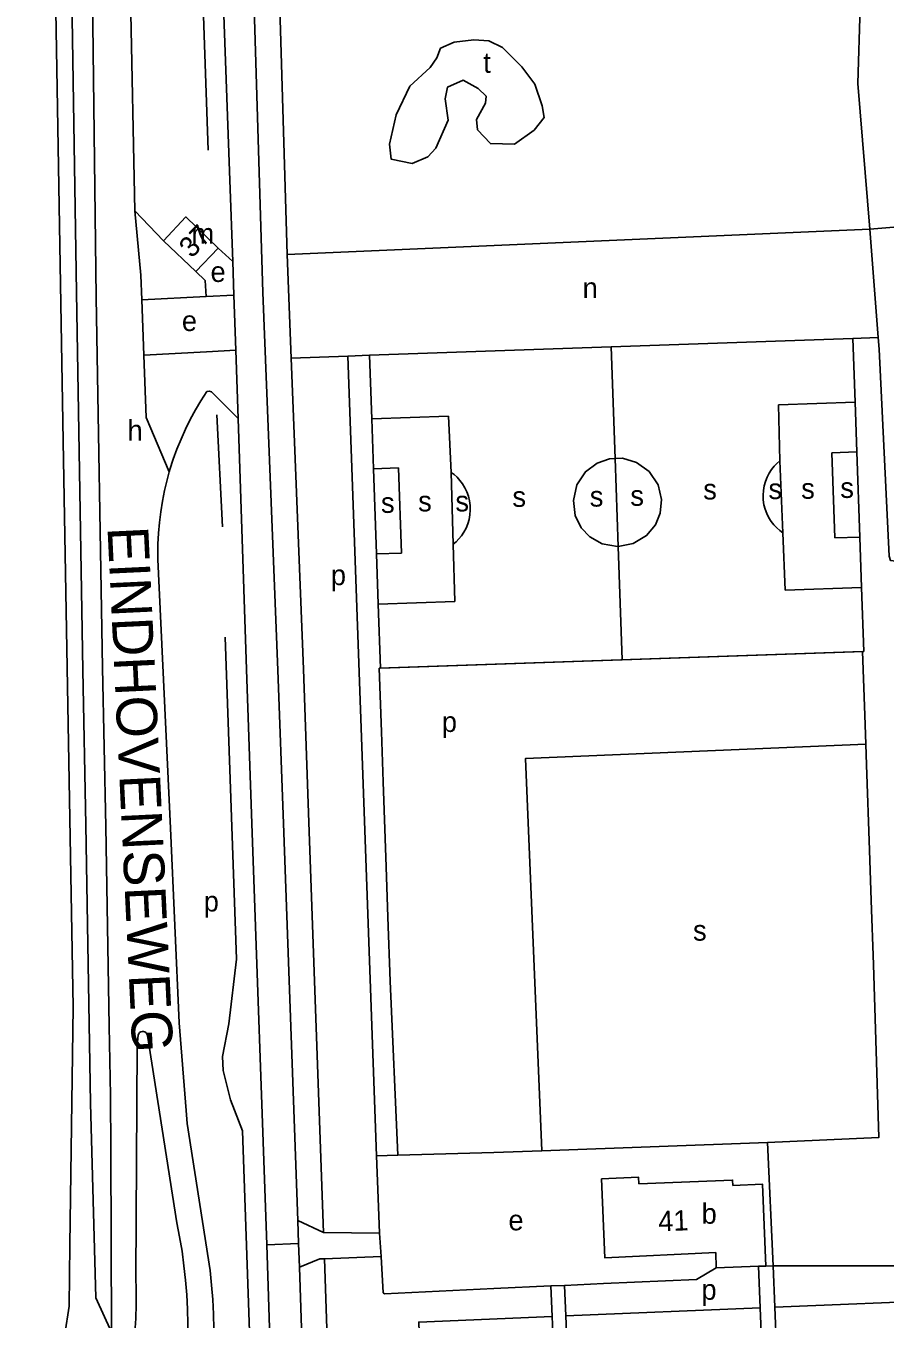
# Model space of a CAD drawing. Extents: x 161394 to 163917, y 388470 to 389774.
# Drawn here: x 162508 to 162676.9, y 388716.6 to 388970.5 of the extents above; entities that cross this region are included whole.
import ezdxf

# ---------------------------------------------------------------- set-up
doc = ezdxf.new("R2010")
doc.units = 0
for name, color, linetype in [('BLT_Basislijn', 7, 'Continuous'), ('BLT_Bebouwing', 7, 'Continuous'), ('BLT_Centroide', 7, 'Continuous'), ('BLT_Huisnummer', 7, 'Continuous'), ('BLT_Straatnaam_hoofdweg', 7, 'Continuous'), ('BLT_Vlakafsluiter', 7, 'Continuous')]:
    doc.layers.add(name, color=color, linetype=linetype)

msp = doc.modelspace()

# ---------------------------------------------------------------- linework, layer by layer
at = {"layer": 'BLT_Basislijn'}
for p, q in [((162538.95, 389085.25), (162543.89, 388946.03)), ((162516.76, 388999.19), (162518, 388918.12)), ((162520.84, 389000), (162521.88, 388917.19)), ((162528.09, 388999.66), (162529.49, 388934.12)), ((162545.97, 389000), (162548.13, 388940.14)), ((162552.14, 389000), (162554.64, 388918.12)), ((162557.14, 389000.18), (162559.42, 388925.59)), ((162548.13, 388940.14), (162548.7, 388924.21)), ((162535.08, 388928.29), (162529.49, 388934.12)), ((162559.42, 388925.59), (162673.87, 388930.56)), ((162673.87, 388930.56), (162681.74, 388931.22)), ((162673.87, 388930.56), (162675.54, 388909.29)), ((162545.85, 388926.81), (162548.7, 388924.21)), ((162559.42, 388925.59), (162560.16, 388905.25)), ((162548.7, 388924.21), (162548.94, 388917.62)), ((162530.66, 388921.5), (162530.83, 388916.7)), ((162518, 388918.12), (162519.24, 388843.98)), ((162530.83, 388916.7), (162543.49, 388917.34)), ((162543.49, 388917.34), (162548.94, 388917.62)), ((162548.94, 388917.62), (162549.3, 388906.81)), ((162554.64, 388918.12), (162557.59, 388843.98)), ((162521.88, 388917.19), (162523.12, 388844.44)), ((162530.83, 388916.7), (162531.23, 388905.84)), ((162575.6, 388905.79), (162623.08, 388907.44)), ((162670.55, 388909.09), (162623.08, 388907.44)), ((162623.84, 388885.51), (162623.08, 388907.44)), ((162675.54, 388909.29), (162670.55, 388909.09)), ((162670.55, 388909.09), (162670.99, 388896.6)), ((162675.54, 388909.29), (162675.72, 388906.98)), ((162543.56, 388906.5), (162531.23, 388905.84)), ((162531.23, 388905.84), (162531.68, 388893.59)), ((162549.3, 388906.81), (162543.56, 388906.5)), ((162549.3, 388906.81), (162549.74, 388893.41)), ((162560.16, 388905.25), (162571.28, 388905.64)), ((162560.16, 388905.25), (162562.59, 388844.18)), ((162571.28, 388905.64), (162575.6, 388905.79)), ((162571.28, 388905.64), (162576.96, 388748.59)), ((162575.6, 388905.79), (162576.04, 388893.3)), ((162545.21, 388897.95), (162549.74, 388893.41)), ((162670.99, 388896.6), (162655.96, 388896.08)), ((162656.2, 388885.06), (162655.96, 388896.08)), ((162670.99, 388896.6), (162671.33, 388886.81)), ((162545.55, 388894.08), (162546.68, 388872.08)), ((162549.74, 388893.41), (162551.38, 388844.13)), ((162576.04, 388893.3), (162591.06, 388893.82)), ((162576.04, 388893.3), (162576.38, 388883.5)), ((162591.59, 388882.81), (162591.06, 388893.82)), ((162515.41, 388888.91), (162517.37, 388777.82)), ((162671.33, 388886.81), (162666.42, 388886.64)), ((162671.33, 388886.81), (162671.91, 388870.09)), ((162624.44, 388868.28), (162623.84, 388885.51)), ((162656.78, 388870.93), (162656.2, 388885.06)), ((162667, 388869.92), (162666.42, 388886.64)), ((162576.38, 388883.5), (162581.29, 388883.67)), ((162576.38, 388883.5), (162576.96, 388866.79)), ((162581.87, 388866.96), (162581.29, 388883.67)), ((162591.99, 388868.68), (162591.59, 388882.81)), ((162657.23, 388859.68), (162656.78, 388870.93)), ((162671.91, 388870.09), (162667, 388869.92)), ((162671.91, 388870.09), (162672.25, 388860.2)), ((162576.96, 388866.79), (162581.87, 388866.96)), ((162576.96, 388866.79), (162577.3, 388856.9)), ((162592.33, 388857.42), (162591.99, 388868.68)), ((162625.21, 388846), (162624.44, 388868.28)), ((162533.99, 388865.73), (162536.48, 388812.96)), ((162672.25, 388860.2), (162657.23, 388859.68)), ((162672.25, 388860.2), (162672.69, 388847.65)), ((162577.3, 388856.9), (162592.33, 388857.42)), ((162577.3, 388856.9), (162577.74, 388844.35)), ((162672.43, 388847.64), (162624.95, 388845.99)), ((162672.69, 388847.65), (162625.21, 388846)), ((162672.86, 388835.15), (162672.43, 388847.64)), ((162519.24, 388843.98), (162519.86, 388813.58)), ((162523.12, 388844.44), (162523.74, 388813.27)), ((162551.38, 388844.13), (162552.47, 388813.89)), ((162557.59, 388843.98), (162558.68, 388813.89)), ((162562.59, 388844.18), (162563.67, 388814.07)), ((162577.48, 388844.34), (162624.95, 388845.99)), ((162577.48, 388844.34), (162577.91, 388831.85)), ((162577.74, 388844.35), (162625.21, 388846)), ((162673.06, 388829.42), (162672.86, 388835.15)), ((162577.91, 388831.85), (162578.25, 388822.05)), ((162673.2, 388825.36), (162673.06, 388829.42)), ((162673.79, 388808.64), (162673.2, 388825.36)), ((162578.25, 388822.05), (162578.83, 388805.34)), ((162523.74, 388813.27), (162524.43, 388774.07)), ((162552.47, 388813.89), (162555.37, 388731.17)), ((162558.68, 388813.89), (162561.47, 388735.9)), ((162563.67, 388814.07), (162566.55, 388733.6)), ((162536.48, 388812.96), (162538.18, 388774.73)), ((162674.13, 388798.76), (162673.79, 388808.64)), ((162578.83, 388805.34), (162579.18, 388795.45)), ((162674.13, 388798.76), (162674.57, 388786.2)), ((162579.18, 388795.45), (162579.61, 388782.9)), ((162531.98, 388772.26), (162537.72, 388735.49)), ((162654.9, 388727), (162653.8, 388751.24)), ((162581.15, 388748.77), (162576.96, 388748.59)), ((162576.96, 388748.59), (162577.26, 388740.3)), ((162577.56, 388733.41), (162577.26, 388740.3)), ((162561.47, 388735.9), (162561.63, 388731.39)), ((162566.55, 388733.6), (162577.56, 388733.41)), ((162577.84, 388728.83), (162577.56, 388733.41)), ((162555.37, 388731.17), (162556.16, 388708.53)), ((162561.63, 388731.39), (162561.79, 388726.76)), ((162566.73, 388728.42), (162577.84, 388728.83)), ((162566.73, 388728.42), (162568.91, 388664.72)), ((162577.84, 388728.83), (162578.27, 388721.71)), ((162652, 388726.94), (162652.33, 388718.79)), ((162654.9, 388727), (162653.43, 388726.99)), ((162686.42, 388727.02), (162654.9, 388727)), ((162654.9, 388727), (162655.22, 388718.91)), ((162561.79, 388726.76), (162563.92, 388664.51)), ((162613.86, 388723.19), (162611.22, 388723.07)), ((162611.22, 388723.07), (162611.46, 388717.08)), ((162613.86, 388723.19), (162621.52, 388723.55)), ((162613.86, 388723.19), (162614.13, 388717.19)), ((162521.83, 388720.73), (162524.91, 388714.01)), ((162611.46, 388717.08), (162613.21, 388673.69)), ((162652.33, 388718.79), (162614.13, 388717.19)), ((162614.13, 388717.19), (162616.07, 388673.8)), ((162652.33, 388718.79), (162654.08, 388675.36)), ((162655.22, 388718.91), (162656.98, 388675.48))]:
    msp.add_line(p, q, dxfattribs=at)
for points in [[(162513.46, 389000), (162514.2, 388958.22), (162515.41, 388888.91)], [(162673.87, 388930.56), (162671.51, 388959.15), (162671.97, 388974.2)], [(162543.49, 388917.34), (162543.27, 388920.48), (162541.47, 388922.21)], [(162675.72, 388906.98), (162677.67, 388866.38), (162677.92, 388865.51), (162722.16, 388860.01)], [(162543.62, 388898.66), (162542.46, 388896.88), (162541.38, 388895.05), (162540.36, 388893.18), (162539.41, 388891.28), (162538.54, 388889.35), (162537.74, 388887.38), (162537.01, 388885.38), (162536.36, 388883.36), (162536.24, 388882.93)], [(162543.62, 388898.66), (162544.07, 388898.76), (162544.51, 388898.59), (162545.21, 388897.95)], [(162622.72, 388885.47), (162620.3, 388884.64), (162618, 388882.92), (162616.3, 388880.33), (162615.62, 388877.27), (162616.01, 388874.33), (162617.19, 388871.94), (162618.88, 388870.14), (162621.31, 388868.78), (162624.3, 388868.25), (162624.44, 388868.28)], [(162623.84, 388885.51), (162622.72, 388885.47)], [(162624.44, 388868.28), (162627.39, 388868.82), (162630, 388870.39), (162631.77, 388872.52), (162632.71, 388874.81), (162632.96, 388877.46), (162632.27, 388880.35), (162630.54, 388882.96), (162628.03, 388884.77), (162625.27, 388885.56), (162623.84, 388885.51)], [(162656.78, 388870.93), (162656.17, 388871.38), (162655.58, 388871.91), (162655.01, 388872.5), (162654.49, 388873.17), (162654.03, 388873.91), (162653.63, 388874.71), (162653.31, 388875.57), (162653.08, 388876.46), (162652.94, 388877.38), (162652.9, 388878.32), (162652.96, 388879.25), (162653.12, 388880.16), (162653.37, 388881.04), (162653.7, 388881.87), (162654.11, 388882.64), (162654.57, 388883.35), (162655.08, 388883.99), (162655.63, 388884.56), (162656.2, 388885.06)], [(162536.24, 388882.93), (162535.79, 388881.31), (162535.29, 388879.25), (162534.88, 388877.17), (162534.54, 388875.07), (162534.28, 388872.96), (162534.1, 388870.84), (162534, 388868.72), (162533.98, 388866.6), (162533.99, 388865.73)], [(162591.99, 388868.68), (162592.57, 388869.17), (162593.13, 388869.73), (162593.65, 388870.37), (162594.12, 388871.07), (162594.53, 388871.84), (162594.88, 388872.67), (162595.14, 388873.54), (162595.3, 388874.45), (162595.38, 388875.38), (162595.35, 388876.32), (162595.22, 388877.24), (162595, 388878.14), (162594.69, 388879), (162594.31, 388879.8), (162593.85, 388880.55), (162593.34, 388881.22), (162592.78, 388881.83), (162592.19, 388882.36), (162591.59, 388882.81)], [(162547.2, 388850.46), (162549.44, 388787.2), (162547.93, 388774.53), (162546.67, 388768.1), (162546.83, 388765.36), (162548.25, 388759.6), (162550.62, 388753.55), (162552.08, 388712.21)], [(162673.06, 388829.42), (162606.24, 388826.64), (162609.45, 388749.6)], [(162519.86, 388813.58), (162520.76, 388758.96), (162521.83, 388720.73)], [(162674.57, 388786.2), (162675.62, 388752.21), (162653.8, 388751.24)], [(162581.15, 388748.77), (162579.61, 388782.9)], [(162504.76, 388692.48), (162508.27, 388698.15), (162509.67, 388697.38), (162515.69, 388713.62), (162516.59, 388719.1), (162516.71, 388731.13), (162517.37, 388777.82)], [(162524.43, 388774.07), (162524.66, 388760.48), (162524.77, 388749.73), (162524.91, 388714.01)], [(162530.11, 388772.35), (162530.23, 388772.6), (162530.41, 388772.81), (162530.64, 388772.96), (162530.9, 388773.04)], [(162530.9, 388773.04), (162531.18, 388773.04), (162531.45, 388772.96), (162531.68, 388772.8), (162531.85, 388772.59), (162531.98, 388772.26)], [(162538.18, 388774.73), (162539.58, 388757.49), (162539.74, 388755), (162544.24, 388726.11)], [(162530.11, 388772.35), (162529.95, 388770.13), (162529.64, 388724.93)], [(162653.8, 388751.24), (162609.45, 388749.6)], [(162609.45, 388749.6), (162600, 388749.26), (162581.15, 388748.77)], [(162537.72, 388735.49), (162538.26, 388732.69), (162538.73, 388729.88), (162539.12, 388727.05), (162539.43, 388724.21), (162539.66, 388721.36), (162539.81, 388718.51), (162539.89, 388715.66), (162539.88, 388712.81), (162539.79, 388709.95), (162539.62, 388707.1), (162539.37, 388704.26), (162539.04, 388701.42), (162538.63, 388698.6), (162538.15, 388695.79), (162537.58, 388692.99), (162536.94, 388690.21), (162536.22, 388687.44), (162535.16, 388683.8)], [(162566.55, 388733.6), (162561.47, 388735.9)], [(162561.79, 388726.76), (162565.78, 388728.38), (162566.73, 388728.42)], [(162529.64, 388724.93), (162529.72, 388722.18), (162529.71, 388719.43), (162529.63, 388716.69), (162529.46, 388713.95), (162529.22, 388711.21), (162528.9, 388708.48), (162528.49, 388705.76), (162528.01, 388703.06), (162527.45, 388700.37), (162526.81, 388697.7), (162526.1, 388695.04), (162525.31, 388692.41), (162524.43, 388689.81), (162523.84, 388687.86)], [(162544.24, 388726.11), (162544.55, 388723.26), (162544.78, 388720.41), (162544.93, 388717.55), (162545, 388714.68), (162544.99, 388711.82), (162544.9, 388708.96), (162544.74, 388706.1), (162544.49, 388703.25), (162544.16, 388700.4), (162543.56, 388696.2)], [(162643.71, 388726.6), (162639.79, 388724.37), (162621.52, 388723.55)], [(162578.27, 388721.71), (162578.53, 388721.55), (162600, 388722.55), (162611.22, 388723.07)], [(162694.37, 388677.01), (162692.86, 388717.9), (162690.62, 388720.38), (162655.22, 388718.91)], [(162611.46, 388717.08), (162585.25, 388715.98), (162586.74, 388672.6)]]:
    msp.add_lwpolyline(points, dxfattribs=at)
msp.add_lwpolyline([(162589.51, 388966.09), (162592.23, 388967.24), (162596.1, 388967.74), (162599.04, 388967.53), (162601.69, 388966.24), (162605.48, 388962.44), (162608.06, 388959), (162609.49, 388954.78), (162609.87, 388952.5), (162607.95, 388950.02), (162604.08, 388947.23), (162599.32, 388947.37), (162596.8, 388950.07), (162596.61, 388952.08), (162598.34, 388955.28), (162598.48, 388956.69), (162596.91, 388958.2), (162593.96, 388959.8), (162590.9, 388958.45), (162590.44, 388956.14), (162591.01, 388951.98), (162588.6, 388946.48), (162587.02, 388944.75), (162583.93, 388943.45), (162579.82, 388944.32), (162579.48, 388947.25), (162580.84, 388952.99), (162583.49, 388958.64), (162587.5, 388962.3), (162588.79, 388964.16)], close=True, dxfattribs=at)
at = {"layer": 'BLT_Bebouwing'}
for p, q in [((162541.47, 388922.21), (162535.08, 388928.29)), ((162545.85, 388926.81), (162541.47, 388922.21)), ((162652, 388726.94), (162643.71, 388726.6)), ((162653.43, 388726.99), (162652, 388726.94))]:
    msp.add_line(p, q, dxfattribs=at)
for points in [[(162535.08, 388928.29), (162539.51, 388932.95), (162545.85, 388926.81)], [(162643.71, 388726.6), (162643.59, 388729.61), (162621.8, 388728.6), (162621.16, 388744.1), (162628.44, 388744.4), (162628.52, 388743.13), (162646.92, 388743.87), (162646.96, 388742.82), (162652.79, 388743.05), (162653.43, 388726.99)]]:
    msp.add_lwpolyline(points, dxfattribs=at)
at = {"layer": 'BLT_Vlakafsluiter'}
for p, q in [((162530.66, 388921.5), (162529.49, 388934.12)), ((162531.68, 388893.59), (162536.24, 388882.93)), ((162561.63, 388731.39), (162555.37, 388731.17))]:
    msp.add_line(p, q, dxfattribs=at)

# ---------------------------------------------------------------- texts
at = {"layer": 'BLT_Centroide'}
for s, p in [('t', (162597.92, 388961.25)), ('m', (162540.6, 388927.69)), ('e', (162544.34, 388920.19)), ('n', (162617.44, 388917.03)), ('e', (162538.71, 388910.55)), ('h', (162528.03, 388889.06)), ('s', (162603.65, 388876.03)), ('s', (162618.85, 388876.09)), ('s', (162626.82, 388876.24)), ('s', (162641.14, 388877.48)), ('s', (162653.96, 388877.56)), ('s', (162660.39, 388877.63)), ('s', (162668.07, 388877.79)), ('s', (162577.83, 388874.85)), ('s', (162585.13, 388875.14)), ('s', (162592.45, 388875.14)), ('p', (162567.98, 388860.66)), ('p', (162589.78, 388831.84)), ('p', (162543, 388796.59)), ('s', (162639.14, 388790.87)), ('b', (162640.83, 388735.28)), ('e', (162602.87, 388733.99)), ('p', (162640.79, 388720.36))]:
    msp.add_text(s, height=4, dxfattribs=at).set_placement(p)
at = {"layer": 'BLT_Huisnummer'}
for s, rotation, p in [('37', 46.4101, (162540.65, 388924.7)), ('41', 2.3042, (162632.37, 388733.77))]:
    msp.add_text(s, height=4, rotation=rotation, dxfattribs=at).set_placement(p)
at = {"layer": 'BLT_Straatnaam_hoofdweg'}
msp.add_text('EINDHOVENSEWEG', height=8, rotation=272.7375, dxfattribs=at).set_placement((162524.08, 388872.03))

doc.saveas('drawing.dxf')
